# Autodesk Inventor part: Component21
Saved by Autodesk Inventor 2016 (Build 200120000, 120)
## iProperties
Created: 2016-09
Part Number: Component21
Material: Generic
Document SubType Name: Modeling
Designer: Administrator
Appearance: Generic
Author: Administrator
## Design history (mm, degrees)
feature "Body1"
body "Solid1"
